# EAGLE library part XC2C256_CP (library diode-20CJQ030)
Xilinx XC2C256 CoolRunner-II CPLD Description: The CoolRunner-II 256-macrocell device is designed for both high performance and low power applications. This lends power savings to high-end communication equipment and high speed to battery operated devices. Due to the low power stand-by and dynamic operation, overall system reliability is improved This device consists of sixteen Function Blocks inter-connected by a low power Advanced Interconnect Matrix (AIM). The AIM feeds 40 true and complement inputs to each Function Block. The Function Blocks consist of a 40 by 56 P-term PLA and 16 macrocells which contain numerous configuration bits that allow for combinational or registered modes of operation. Additionally, these registers can be globally reset or preset and configured as a D or T flip-flop or as a D latch. There are also multiple clock signals, both global and local product term types, configured on a per macrocell basis. Output pin configurations include slew rate limit, bus hold, pull-up, open drain and programmable grounds. A Schmitt-trigger input is available on a per input pin basis. In addition to storing macrocell output states, the macrocell registers may be configured as "direct input" registers to store signals directly from input pins. Clocking is available on a global or Function Block basis. Three global clocks are available for all Function Blocks as a synchronous clock source. Macrocell registers can be individually configured to power up to the zero or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
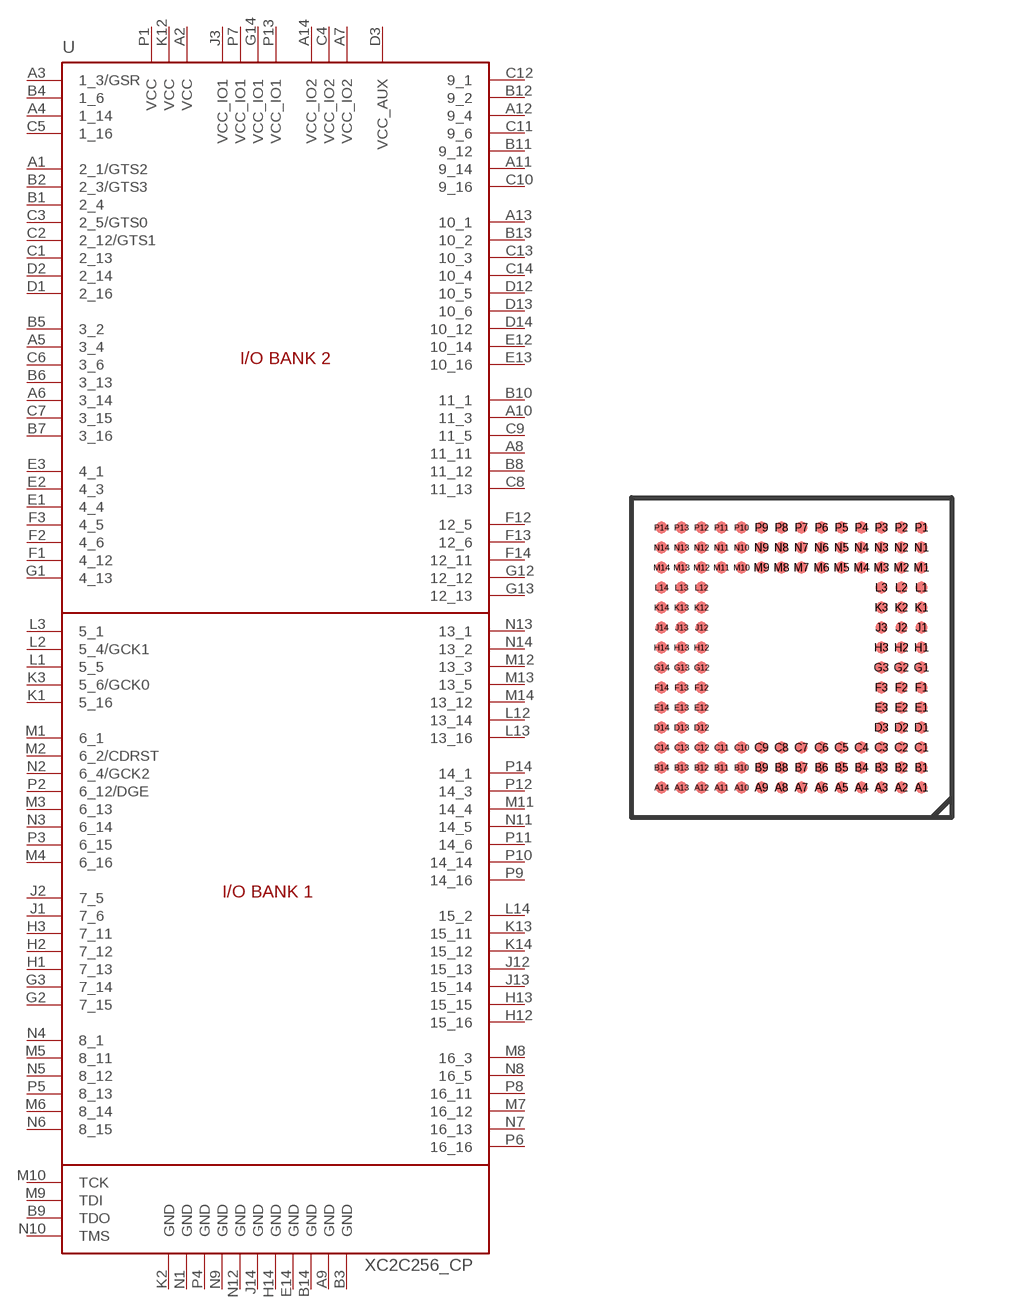
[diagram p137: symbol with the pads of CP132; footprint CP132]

Designator prefix U

## XC2C256_CP  [CP132]
A1  2_1/GTS2
A2  VCC  pwr
A3  1_3/GSR
A4  1_14
A5  3_4
A6  3_14
A7  VCC_IO2  pwr
A8  11_11
A9  GND  pwr
A10  11_3
A11  9_14
A12  9_4
A13  10_1
A14  VCC_IO2  pwr
B1  2_4
B2  2_3/GTS3
B3  GND  pwr
B4  1_6
B5  3_2
B6  3_13
B7  3_16
B8  11_12
B9  TDO
B10  11_1
B11  9_12
B12  9_2
B13  10_2
B14  GND  pwr
C1  2_13
C2  2_12/GTS1
C3  2_5/GTS0
C4  VCC_IO2  pwr
C5  1_16
C6  3_6
C7  3_15
C8  11_13
C9  11_5
C10  9_16
C11  9_6
C12  9_1
C13  10_3
C14  10_4
D1  2_16
D2  2_14
D3  VCC_AUX  pwr
D12  10_5
D13  10_6
D14  10_12
E1  4_4
E2  4_3
E3  4_1
E12  10_14
E13  10_16
E14  GND  pwr
F1  4_12
F2  4_6
F3  4_5
F12  12_5
F13  12_6
F14  12_11
G1  4_13
G2  7_15
G3  7_14
G12  12_12
G13  12_13
G14  VCC_IO1  pwr
H1  7_13
H2  7_12
H3  7_11
H12  15_16
H13  15_15
H14  GND  pwr
J1  7_6
J2  7_5
J3  VCC_IO1  pwr
J12  15_13
J13  15_14
J14  GND  pwr
K1  5_16
K2  GND  pwr
K3  5_6/GCK0
K12  VCC  pwr
K13  15_11
K14  15_12
L1  5_5
L2  5_4/GCK1
L3  5_1
L12  13_14
L13  13_16
L14  15_2
M1  6_1
M2  6_2/CDRST
M3  6_13
M4  6_16
M5  8_11
M6  8_14
M7  16_12
M8  16_3
M9  TDI
M10  TCK
M11  14_4
M12  13_3
M13  13_5
M14  13_12
N1  GND  pwr
N2  6_4/GCK2
N3  6_14
N4  8_1
N5  8_12
N6  8_15
N7  16_13
N8  16_5
N9  GND  pwr
N10  TMS
N11  14_5
N12  GND  pwr
N13  13_1
N14  13_2
P1  VCC  pwr
P2  6_12/DGE
P3  6_15
P4  GND  pwr
P5  8_13
P6  16_16
P7  VCC_IO1  pwr
P8  16_11
P9  14_16
P10  14_14
P11  14_6
P12  14_3
P13  VCC_IO1  pwr
P14  14_1

## Footprint CP132 (pad centres in mm)
XILINX Chip Scale BGA (CP132/CPG132) Package
smd 0.3 x 0.3: A1 3.25,-3.25; A2 2.75,-3.25; A3 2.25,-3.25; A4 1.75,-3.25; A5 1.25,-3.25; A6 0.75,-3.25; A7 0.25,-3.25; A8 -0.25,-3.25; A9 -0.75,-3.25; A10 -1.25,-3.25; A11 -1.75,-3.25; A12 -2.25,-3.25; A13 -2.75,-3.25; A14 -3.25,-3.25; B1 3.25,-2.75; B2 2.75,-2.75; B3 2.25,-2.75; B4 1.75,-2.75; B5 1.25,-2.75; B6 0.75,-2.75; B7 0.25,-2.75; B8 -0.25,-2.75; B9 -0.75,-2.75; B10 -1.25,-2.75; B11 -1.75,-2.75; B12 -2.25,-2.75; B13 -2.75,-2.75; B14 -3.25,-2.75; C1 3.25,-2.25; C2 2.75,-2.25; C3 2.25,-2.25; C4 1.75,-2.25; C5 1.25,-2.25; C6 0.75,-2.25; C7 0.25,-2.25; C8 -0.25,-2.25; C9 -0.75,-2.25; C10 -1.25,-2.25; C11 -1.75,-2.25; C12 -2.25,-2.25; C13 -2.75,-2.25; C14 -3.25,-2.25; D1 3.25,-1.75; D2 2.75,-1.75; D3 2.25,-1.75; D12 -2.25,-1.75; D13 -2.75,-1.75; D14 -3.25,-1.75; E1 3.25,-1.25; E2 2.75,-1.25; E3 2.25,-1.25; E12 -2.25,-1.25; E13 -2.75,-1.25; E14 -3.25,-1.25; F1 3.25,-0.75; F2 2.75,-0.75; F3 2.25,-0.75; F12 -2.25,-0.75; F13 -2.75,-0.75; F14 -3.25,-0.75; G1 3.25,-0.25; G2 2.75,-0.25; G3 2.25,-0.25; G12 -2.25,-0.25; G13 -2.75,-0.25; G14 -3.25,-0.25; H1 3.25,0.25; H2 2.75,0.25; H3 2.25,0.25; H12 -2.25,0.25; H13 -2.75,0.25; H14 -3.25,0.25; J1 3.25,0.75; J2 2.75,0.75; J3 2.25,0.75; J12 -2.25,0.75; J13 -2.75,0.75; J14 -3.25,0.75; K1 3.25,1.25; K2 2.75,1.25; K3 2.25,1.25; K12 -2.25,1.25; K13 -2.75,1.25; K14 -3.25,1.25; L1 3.25,1.75; L2 2.75,1.75; L3 2.25,1.75; L12 -2.25,1.75; L13 -2.75,1.75; L14 -3.25,1.75; M1 3.25,2.25; M2 2.75,2.25; M3 2.25,2.25; M4 1.75,2.25; M5 1.25,2.25; M6 0.75,2.25; M7 0.25,2.25; M8 -0.25,2.25; M9 -0.75,2.25; M10 -1.25,2.25; M11 -1.75,2.25; M12 -2.25,2.25; M13 -2.75,2.25; M14 -3.25,2.25; N1 3.25,2.75; N2 2.75,2.75; N3 2.25,2.75; N4 1.75,2.75; N5 1.25,2.75; N6 0.75,2.75; N7 0.25,2.75; N8 -0.25,2.75; N9 -0.75,2.75; N10 -1.25,2.75; N11 -1.75,2.75; N12 -2.25,2.75; N13 -2.75,2.75; N14 -3.25,2.75; P1 3.25,3.25; P2 2.75,3.25; P3 2.25,3.25; P4 1.75,3.25; P5 1.25,3.25; P6 0.75,3.25; P7 0.25,3.25; P8 -0.25,3.25; P9 -0.75,3.25; P10 -1.25,3.25; P11 -1.75,3.25; P12 -2.25,3.25; P13 -2.75,3.25; P14 -3.25,3.25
